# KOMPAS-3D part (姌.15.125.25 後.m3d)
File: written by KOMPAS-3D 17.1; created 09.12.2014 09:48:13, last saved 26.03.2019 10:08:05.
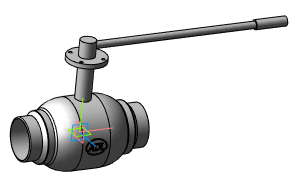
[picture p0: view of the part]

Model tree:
1. Операция без истории:5  (labels: Сталь 20  ГОСТ 1050-88)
